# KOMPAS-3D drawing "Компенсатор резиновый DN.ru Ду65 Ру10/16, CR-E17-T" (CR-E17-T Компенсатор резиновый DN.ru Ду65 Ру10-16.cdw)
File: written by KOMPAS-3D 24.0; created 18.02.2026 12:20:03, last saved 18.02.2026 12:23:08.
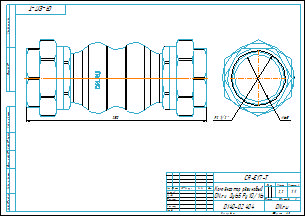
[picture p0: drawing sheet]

Document properties: Типовые: Типовые; Автор: DN.RU; Форматы листов документа: A3; Полное имя файла: CR-E17-T Компенсатор резиновый DN.ru Ду65 Ру10-16.m3d; Масса: 2.2; Наименование: Компенсатор резиновый DN.ru Ду65 Ру10/16; Количество листов документа: 1; Комментарий: D140-02404; Примечание: D140-02404

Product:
- Body: Твердое тело1  | qty 1
    Масса: 5.04771
- Part/product: Компенсатор резиновый DN.ru Ду65 Ру10/16  | designation CR-E17-T
    Масса: 2.2
    Раздел спецификации: Прочие изделия
    Форматы листов документа: A3
    Комментарий: D140-02404
    Примечание: D140-02404
    additional columns: Типовые

Views: Вид 1, Справа, Проекционный вид 2
Referenced files in D:\Работа\Компенсаторы\CR-Е17-T Компенсатор резиновый DN.ru Ду15-80\DN65\: CR-E17-T Компенсатор резиновый DN.ru Ду65 Ру10-16.m3d, CR-E17-T Компенсатор резиновый DN.ru Ду65 Ру10-16.cdw
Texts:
  Линейный размер
  CR-E17-T
  Диаметральный размер
  Компенсатор резиновый
  DN.ru Ду65 Ру10/16
  Твердое тело1
  Компенсатор резиновый DN.ru Ду65 Ру10/16
  CR-E17-T Компенсатор резиновый DN.ru Ду65 Ру10/16
Dimensions and other numbers on the sheet: 0; 3; 2; 4; 250; 65; 1:1; 1; 2,2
